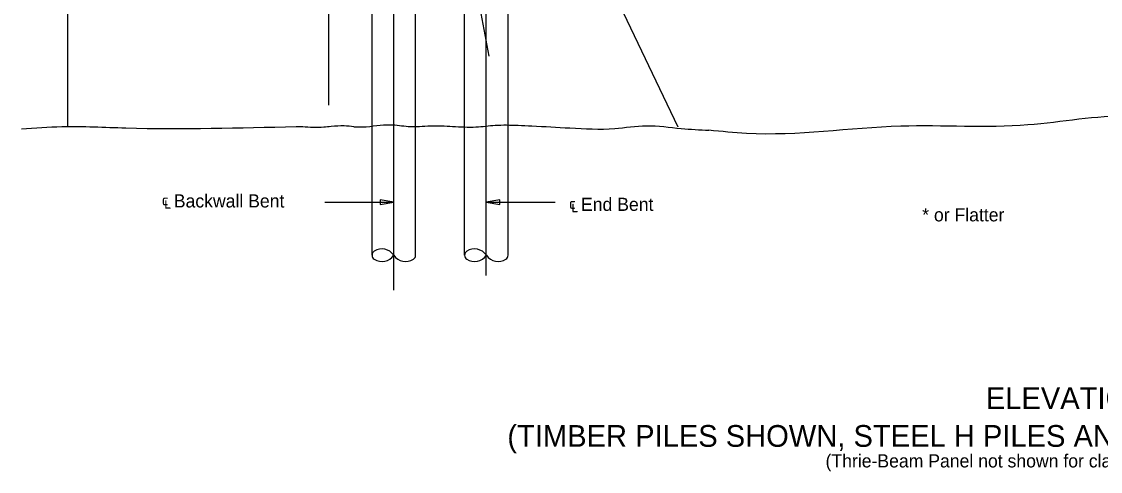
# Model space of a CAD drawing. Extents: x 3 to 58.1, y 3.3 to 34.2.
# Drawn here: x 3.78 to 28.56, y 3.34 to 13.68 of the extents above; entities that cross this region are included whole.
import ezdxf

# ---------------------------------------------------------------- set-up
doc = ezdxf.new("R2010")
doc.units = 0
for name, color, linetype in [('CL_Minor', 7, 'Continuous'), ('Dimension', 7, 'Continuous'), ('GroundLines', 7, 'Continuous'), ('TextStructures', 7, 'Continuous'), ('Wood_h', 7, 'Continuous')]:
    doc.layers.add(name, color=color, linetype=linetype)

msp = doc.modelspace()

# ---------------------------------------------------------------- linework, layer by layer
at = {"layer": 'CL_Minor'}
for p, q in [((14.456, 7.843), (14.456, 30.289)), ((12.331, 7.505), (12.331, 24.87))]:
    msp.add_line(p, q, dxfattribs=at)
at = {"layer": 'Dimension'}
for p, q in [((10.842, 11.759), (10.842, 25.063)), ((4.842, 11.264), (4.842, 22.282)), ((14.518, 12.884), (13.24, 19.761)), ((18.861, 11.255), (16.66, 15.864)), ((10.745, 9.53), (12.331, 9.53)), ((14.456, 9.53), (16.037, 9.53))]:
    msp.add_line(p, q, dxfattribs=at)
for points in [[(12.331, 9.53), (12.019, 9.583), (12.019, 9.477)], [(14.456, 9.53), (14.768, 9.477), (14.768, 9.583)]]:
    msp.add_lwpolyline(points, close=True, dxfattribs=at)
at = {"layer": 'GroundLines'}
for points in [[(42.508, 11.295), (40.547, 11.246), (39.901, 11.274), (39.367, 11.359), (37.934, 11.274), (35.758, 11.258), (34.367, 11.218), (32.541, 11.33), (30.884, 11.33), (29.227, 11.499), (26.896, 11.302), (23.974, 11.274), (20.435, 11.106), (19.569, 11.183)], [(11.416, 11.258), (11.192, 11.281), (10.892, 11.265), (10.722, 11.25), (10.476, 11.242), (10.238, 11.258), (10.092, 11.258), (6.175, 11.227), (4.708, 11.259), (3.782, 11.208)], [(11.416, 11.258), (11.619, 11.258), (12.256, 11.309), (12.663, 11.27), (13.173, 11.283), (13.682, 11.27), (14.217, 11.258), (14.662, 11.296), (15.184, 11.296), (15.503, 11.283)], [(15.503, 11.283), (16.373, 11.234), (17.404, 11.221), (18.13, 11.285), (18.932, 11.221), (19.569, 11.183)]]:
    msp.add_spline(points, degree=3, dxfattribs=at)
at = {"layer": 'Wood_h'}
for p, q in [((11.831, 8.312), (11.831, 22.208)), ((12.831, 8.312), (12.831, 21.484)), ((13.956, 8.312), (13.956, 20.681)), ((14.956, 8.312), (14.956, 20.088))]:
    msp.add_line(p, q, dxfattribs=at)
for centre, radius, start, end in [((12.06, 8.124), 0.329, 34.3251, 123.0426), ((14.185, 8.124), 0.329, 34.3251, 123.0426), ((11.938, 8.309), 0.107, 122.6152, 179.9979), ((11.938, 8.309), 0.107, 179.9979, 237.3848), ((12.06, 8.495), 0.329, 236.955, 325.6725), ((12.603, 8.495), 0.329, 214.3153, 303.0328), ((12.724, 8.309), 0.107, 302.6152, 0.0021), ((14.063, 8.309), 0.107, 122.6152, 179.9979), ((14.063, 8.309), 0.107, 179.9979, 237.3848), ((14.185, 8.495), 0.329, 236.955, 325.6725), ((14.728, 8.495), 0.329, 214.3153, 303.0328), ((14.849, 8.309), 0.107, 302.6152, 0.0021)]:
    msp.add_arc(centre, radius, start, end, dxfattribs=at)

# ---------------------------------------------------------------- texts
at = {"layer": 'Dimension'}
msp.add_text('℄ End Bent', height=0.3024, dxfattribs=at).set_placement((16.354, 9.328))
at = {"layer": 'TextStructures'}
for s, height, p in [('℄ Backwall Bent', 0.3024, (7.002, 9.406)), ('* or Flatter', 0.3024, (24.467, 9.087)), ('ELEVATION VIEW', 0.5, (25.928, 4.776)), ('(TIMBER PILES SHOWN, STEEL H PILES AND STEEL PIPE PILES SIMILAR)', 0.5, (14.939, 3.906)), ('(Thrie-Beam Panel not shown for clarity, See Index 102-240)', 0.3024, (22.247, 3.432))]:
    msp.add_text(s, height=height, dxfattribs=at).set_placement(p)

doc.saveas('drawing.dxf')
